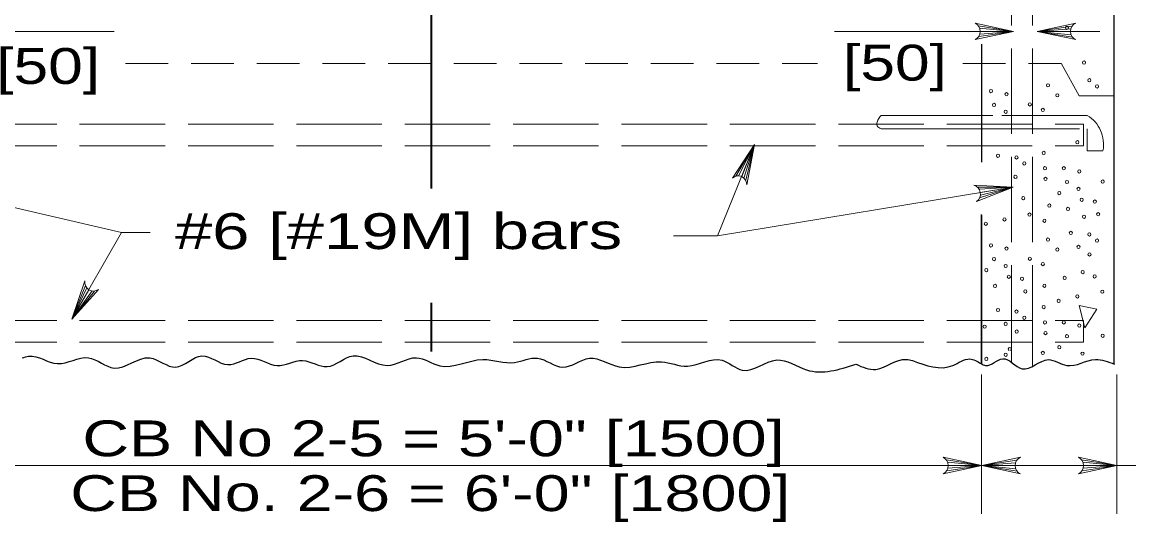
# Model space of a CAD drawing. Extents: x 1329.9 to 1363.9, y 715.5 to 737.5.
# Drawn here: x 1341.364 to 1346.184, y 728.724 to 730.9 of the extents above; entities that cross this region are included whole.
import ezdxf
from ezdxf.enums import TextEntityAlignment as Align

# ---------------------------------------------------------------- set-up
doc = ezdxf.new("R2010")
doc.units = 0
doc.header["$LTSCALE"] = 0.062
doc.linetypes.add('LONG_DASHED', pattern=[7.5, 6, -1.5])
doc.linetypes.add('MEDIUM_DASHED', pattern=[4.5, 3, -1.5])
doc.layers.add('1', color=7, linetype='Continuous', lineweight=13)

msp = doc.modelspace()

# ---------------------------------------------------------------- linework, layer by layer
at = {"layer": '1', "lineweight": 25}
for p, q in [((1346.12017, 729.46942), (1346.12017, 733.98667)), ((1345.54208, 730.80358), (1345.54208, 730.2895)), ((1345.54208, 729.46942), (1345.54208, 730.06192)), ((1345.54208, 730.05958), (1345.54208, 729.46942)), ((1345.54208, 729.41308), (1345.54208, 729.46942)), ((1345.54208, 729.46942), (1345.54208, 729.41308)), ((1346.12017, 729.41025), (1346.12017, 729.46942))]:
    msp.add_line(p, q, dxfattribs=at)
at = {"layer": '1', "lineweight": 35}
msp.add_line((1343.146, 731.695), (1343.146, 730.17492), dxfattribs=at)
at = {"layer": '1'}
for p, q in [((1340.92425, 730.85925), (1341.76567, 730.85925)), ((1344.90192, 730.85925), (1345.68208, 730.85925)), ((1345.528, 730.88417), (1345.68208, 730.85925)), ((1345.52983, 730.83667), (1345.68208, 730.85925)), ((1345.53383, 730.87375), (1345.68208, 730.85925)), ((1345.535, 730.84783), (1345.68208, 730.85925)), ((1345.5365, 730.85925), (1345.68208, 730.85925)), ((1345.93633, 730.88183), (1345.784, 730.85925)), ((1345.93117, 730.87067), (1345.784, 730.85925)), ((1345.784, 730.85925), (1346.05758, 730.85925)), ((1345.92958, 730.85925), (1345.784, 730.85925)), ((1345.93225, 730.84475), (1345.784, 730.85925)), ((1345.93808, 730.83433), (1345.784, 730.85925)), ((1345.59125, 730.4935), (1345.10533, 730.4935)), ((1345.10533, 730.43492), (1345.59617, 730.43492)), ((1344.55333, 730.36667), (1344.392, 729.96875)), ((1344.47292, 730.22917), (1344.55333, 730.36667)), ((1344.48433, 730.23042), (1344.55333, 730.36667)), ((1344.49817, 730.22708), (1344.55333, 730.36667)), ((1344.50758, 730.221), (1344.55333, 730.36667)), ((1344.51542, 730.2115), (1344.55333, 730.36667)), ((1341.79758, 729.9845), (1340.92467, 730.18533)), ((1345.6805, 730.18192), (1344.392, 729.96875)), ((1345.52442, 730.18133), (1345.6805, 730.18192)), ((1345.53183, 730.172), (1345.6805, 730.18192)), ((1345.53392, 730.13475), (1345.6805, 730.18192)), ((1345.53683, 730.15808), (1345.6805, 730.18192)), ((1345.53717, 730.14667), (1345.6805, 730.18192)), ((1345.54208, 730.05725), (1345.54208, 729.46942)), ((1341.58108, 729.60667), (1341.79758, 729.9845)), ((1341.92242, 729.9845), (1341.79758, 729.9845)), ((1344.20017, 729.96875), (1344.392, 729.96875)), ((1341.64017, 729.75283), (1341.58108, 729.60667)), ((1341.64675, 729.74233), (1341.58108, 729.60667)), ((1341.65533, 729.73483), (1341.58108, 729.60667)), ((1341.66867, 729.72942), (1341.58108, 729.60667)), ((1341.68025, 729.729), (1341.58108, 729.60667)), ((1345.54217, 729.36483), (1345.54217, 728.75908)), ((1346.13117, 729.36483), (1346.13117, 728.75908)), ((1345.389, 728.99408), (1345.54308, 728.96908)), ((1345.39483, 728.98358), (1345.54308, 728.96908)), ((1345.69542, 728.99167), (1345.54308, 728.96908)), ((1345.69025, 728.9805), (1345.54308, 728.96908)), ((1345.978, 728.99408), (1346.13208, 728.96908)), ((1345.98383, 728.98358), (1346.13208, 728.96908)), ((1345.39083, 728.94658), (1345.54308, 728.96908)), ((1345.396, 728.95775), (1345.54308, 728.96908)), ((1345.39758, 728.96908), (1345.54308, 728.96908)), ((1345.89383, 728.96908), (1345.54308, 728.96908)), ((1345.68867, 728.96908), (1345.54308, 728.96908)), ((1345.69142, 728.95467), (1345.54308, 728.96908)), ((1345.69725, 728.94417), (1345.54308, 728.96908)), ((1346.13208, 728.96908), (1345.85683, 728.96908)), ((1345.97983, 728.94658), (1346.13208, 728.96908)), ((1345.985, 728.95775), (1346.13208, 728.96908)), ((1347.01083, 728.96908), (1346.13208, 728.96908))]:
    msp.add_line(p, q, dxfattribs=at)
at = {"layer": '1', "linetype": 'MEDIUM_DASHED'}
for p, q in [((1341.8145, 730.71958), (1344.82742, 730.71958)), ((1345.46042, 730.71958), (1345.89092, 730.71958)), ((1345.89092, 730.71908), (1345.96742, 730.57883)), ((1345.96742, 730.57883), (1346.121, 730.57883))]:
    msp.add_line(p, q, dxfattribs=at)
at = {"layer": '1', "linetype": 'LONG_DASHED'}
for p, q in [((1346.00275, 730.4935), (1345.59125, 730.4935)), ((1340.67083, 730.45583), (1345.98667, 730.45583)), ((1345.98667, 730.45583), (1345.98667, 730.36083)), ((1340.67083, 730.36083), (1345.98667, 730.36083)), ((1340.67083, 729.60092), (1345.98667, 729.60092)), ((1345.98667, 729.60092), (1345.98667, 729.50592)), ((1340.67083, 729.50592), (1345.98667, 729.50592))]:
    msp.add_line(p, q, dxfattribs=at)
for points in [[(1345.67267, 729.415), (1345.67267, 729.46942), (1345.67267, 733.37567)], [(1345.76417, 729.40517), (1345.76417, 729.46942), (1345.76417, 733.37567)], [(1345.59617, 730.43492), (1346.00275, 730.43492), (1346.00275, 730.33925), (1346.07108, 730.33925)]]:
    msp.add_lwpolyline(points, dxfattribs=at)
at = {"layer": '1'}
for points in [[(1345.51392, 730.89492), (1345.68208, 730.85925), (1345.51392, 730.82367)], [(1345.95225, 730.82367), (1345.784, 730.85925), (1345.95225, 730.89492)], [(1344.45808, 730.21992), (1344.55333, 730.36667), (1344.52092, 730.19092)], [(1345.50875, 730.18958), (1345.6805, 730.18192), (1345.52033, 730.11925)], [(1341.69625, 729.73558), (1341.58108, 729.60667), (1341.63758, 729.77392)], [(1345.37492, 729.00475), (1345.54308, 728.96908), (1345.37492, 728.9335)], [(1345.71133, 728.9335), (1345.54308, 728.96908), (1345.71133, 729.00475)], [(1345.96392, 729.00475), (1346.13208, 728.96908), (1345.96392, 728.9335)], [(1345.54308, 728.96908), (1344.87642, 728.96908), (1341.09283, 728.96908)]]:
    msp.add_lwpolyline(points, dxfattribs=at)
at = {"layer": '1', "lineweight": 35}
msp.add_lwpolyline([(1343.146, 729.67767), (1343.146, 729.46942), (1343.146, 729.46508)], dxfattribs=at)
at = {"layer": '1'}
msp.add_lwpolyline([(1345.96708, 729.66575), (1345.99275, 729.56842), (1346.045, 729.65058)], close=True, dxfattribs=at)
for centre, major_axis, start_param, end_param in [((1345.50023, 730.85925), (0, -0.03844), 0.3855052, 2.7561184), ((1345.96588, 730.85926), (0, 0.03844), 0.3855052, 2.7561184), ((1344.48432, 730.19234), (0.01358, -0.03596), 1.1898246, 3.5604377), ((1345.50103, 730.1522), (0.00588, -0.03799), 0.3956254, 2.7662386), ((1341.67386, 729.76679), (-0.01662, 0.03466), 0.9579184, 3.3285315), ((1345.66542, 729.47556), (0, 0.00718), 3.6952153, 8.8711553), ((1345.36125, 728.96911), (0, -0.03844), 0.3855052, 2.7561184), ((1345.72499, 728.96912), (0, 0.03844), 0.3855052, 2.7561184), ((1345.95024, 728.96911), (0, -0.03844), 0.3855052, 2.7561184)]:
    msp.add_ellipse(centre, major_axis=major_axis, ratio=0.944544, start_param=start_param, end_param=end_param, dxfattribs=at)
for centre, major_axis in [((1345.91411, 730.87539), (0, 0.00718)), ((1345.98854, 730.72393), (0, 0.00718)), ((1345.83158, 730.62481), (0, 0.00718)), ((1346.01175, 730.64686), (0, 0.00718)), ((1346.04543, 730.62027), (0, 0.00718)), ((1345.58322, 730.59939), (0, 0.00718)), ((1345.65083, 730.58579), (0, 0.00718)), ((1345.87271, 730.58126), (0, 0.00718)), ((1345.59691, 730.53956), (0, 0.00718)), ((1345.75276, 730.54135), (0, 0.00718)), ((1345.80927, 730.51779), (0, 0.00718)), ((1345.6474, 730.50962), (0, 0.00718)), ((1345.95947, 730.37691), (0, 0.00718)), ((1345.81303, 730.33068), (0, 0.00718)), ((1345.61372, 730.31803), (0, 0.00718)), ((1345.69455, 730.31103), (0, 0.00718)), ((1345.72823, 730.28445), (0, 0.00718)), ((1345.69008, 730.2258), (-0.00088, 0.00713)), ((1345.81816, 730.26357), (0, 0.00718)), ((1345.90042, 730.26357), (0, 0.00718)), ((1345.96803, 730.24997), (0, 0.00718)), ((1345.82069, 730.21734), (0, 0.00718)), ((1345.91411, 730.20374), (0, 0.00718)), ((1346.06996, 730.20553), (0, 0.00718)), ((1345.72398, 730.13316), (-0.00088, 0.00713)), ((1345.88064, 730.15566), (0, 0.00718)), ((1345.9646, 730.1738), (0, 0.00718)), ((1345.83756, 730.10098), (0, 0.00718)), ((1345.91834, 730.08676), (0, 0.00718)), ((1345.97834, 730.12667), (0, 0.00718)), ((1346.0357, 730.11844), (0, 0.00718)), ((1345.64227, 730.04109), (0, 0.00718)), ((1345.75101, 730.06197), (0, 0.00718)), ((1345.81615, 730.03476), (0, 0.00718)), ((1345.98854, 730.05228), (0, 0.00718)), ((1346.05024, 730.0632), (0, 0.00718)), ((1345.56085, 730.02206), (0, 0.00718)), ((1345.83158, 729.95316), (0, 0.00718)), ((1345.93092, 729.98221), (0, 0.00718)), ((1346.01175, 729.97521), (0, 0.00718)), ((1346.04543, 729.94863), (0, 0.00718)), ((1345.58322, 729.92775), (0, 0.00718)), ((1345.65083, 729.91415), (0, 0.00718)), ((1345.87271, 729.90961), (0, 0.00718)), ((1345.96433, 729.92142), (0, 0.00718)), ((1346.0126, 729.88846), (0, 0.00718)), ((1345.59691, 729.86792), (0, 0.00718)), ((1345.75276, 729.86971), (0, 0.00718)), ((1345.80927, 729.84614), (0, 0.00718)), ((1345.56344, 729.81984), (0, 0.00718)), ((1345.6474, 729.83797), (0, 0.00718)), ((1345.98262, 729.81139), (0, 0.00718)), ((1346.03486, 729.79236), (0, 0.00718)), ((1345.60114, 729.75094), (0, 0.00718)), ((1345.66114, 729.79085), (0, 0.00718)), ((1345.7185, 729.78262), (0, 0.00718)), ((1345.81615, 729.75178), (0, 0.00718)), ((1345.9038, 729.78603), (0, 0.00718)), ((1345.73304, 729.72737), (0, 0.00718)), ((1345.95947, 729.70527), (0, 0.00718)), ((1346.06821, 729.72614), (0, 0.00718)), ((1345.81303, 729.65903), (0, 0.00718)), ((1345.87805, 729.68624), (0, 0.00718)), ((1345.61372, 729.64639), (0, 0.00718)), ((1345.69455, 729.63939), (0, 0.00718)), ((1345.72823, 729.6128), (0, 0.00718)), ((1345.55551, 729.57379), (0, 0.00718)), ((1345.64713, 729.5856), (0, 0.00718)), ((1345.6954, 729.55264), (0, 0.00718)), ((1345.81816, 729.59193), (0, 0.00718)), ((1345.90042, 729.59193), (0, 0.00718)), ((1345.96803, 729.57833), (0, 0.00718)), ((1345.82069, 729.54569), (0, 0.00718)), ((1345.91411, 729.53209), (0, 0.00718)), ((1346.06996, 729.53388), (0, 0.00718)), ((1345.80927, 729.45945), (0, 0.00718)), ((1345.88064, 729.48402), (0, 0.00718)), ((1345.98167, 729.4562), (0, 0.00718)), ((1345.56344, 729.43314), (0, 0.00718)), ((1345.6474, 729.45128), (0, 0.00718))]:
    msp.add_ellipse(centre, major_axis=major_axis, ratio=0.944544, dxfattribs=at)
at = {"layer": '1', "linetype": 'LONG_DASHED'}
msp.add_ellipse((1345.93655, 730.36649), major_axis=(0, -0.14504), ratio=0.944544, start_param=1.3817766, end_param=2.6372404, dxfattribs=at)
at = {"layer": '1'}
msp.add_spline([(1345.10533, 730.4935), (1345.08742, 730.46442), (1345.08742, 730.449), (1345.10533, 730.43492)], degree=3, dxfattribs=at)
at = {"layer": '1', "lineweight": 25}
for points in [[(1341.36442, 729.43742), (1341.39275, 729.44542), (1341.51858, 729.41275), (1341.65275, 729.43875), (1341.7655, 729.3935), (1341.92017, 729.438), (1342.03292, 729.39758), (1342.14758, 729.44683), (1342.26033, 729.40833), (1342.362, 729.43617), (1342.47467, 729.4045), (1342.58558, 729.42642), (1342.69275, 729.39958), (1342.8055, 729.44692), (1342.95367, 729.40475), (1343.08133, 729.43842), (1343.18292, 729.40375), (1343.37025, 729.43092), (1343.50908, 729.41792), (1343.60792, 729.43683), (1343.71875, 729.39742), (1343.83525, 729.436), (1343.96475, 729.3985), (1344.14842, 729.42075), (1344.26117, 729.40175), (1344.41208, 729.42783), (1344.50058, 729.38433), (1344.65067, 729.42892), (1344.78017, 729.38567), (1344.99492, 729.41017)], [(1344.99492, 729.41017), (1345.08217, 729.38775), (1345.21542, 729.43133), (1345.24133, 729.42592)], [(1345.24133, 729.42592), (1345.4175, 729.40483), (1345.49117, 729.43342), (1345.53942, 729.41325)], [(1345.53942, 729.41325), (1345.56008, 729.40458), (1345.63467, 729.43408), (1345.7185, 729.39058), (1345.83317, 729.43008), (1345.91325, 729.40508), (1346.03825, 729.43108), (1346.12083, 729.41025)]]:
    msp.add_spline(points, degree=3, dxfattribs=at)

# ---------------------------------------------------------------- texts
at = {"layer": '1', "width": 1.3}
for p in [(1341.47771, 730.63092), (1345.16538, 730.64542)]:
    msp.add_text('[50]', height=0.156, dxfattribs=at).set_placement(p, align=Align.CENTER)
at = {"layer": '1'}
for s, width, p in [('#6 [#19M] bars', 1.4, (1342.02958, 729.91175)), ('CB No 2-5 = 5\'-0" [1500]', 1.35, (1341.62683, 729.00942)), ('CB No. 2-6 = 6\'-0" [1800]', 1.35, (1341.57383, 728.77075))]:
    msp.add_text(s, height=0.156, dxfattribs=dict(at, width=width)).set_placement(p)

doc.saveas('drawing.dxf')
